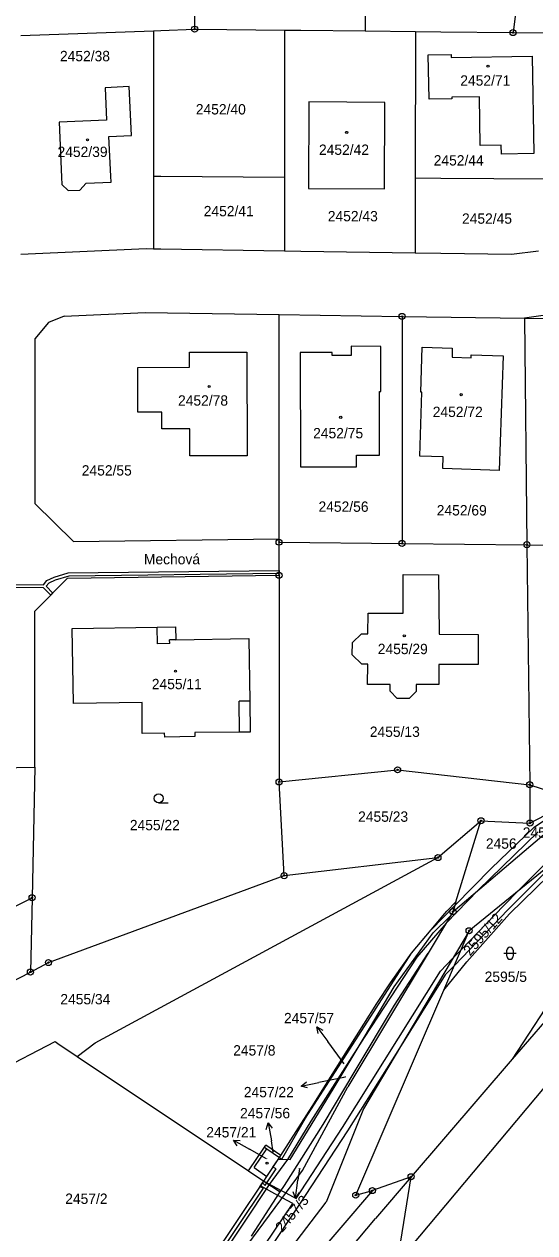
# Model space of a CAD drawing. Extents: x -755819 to -753140, y -1169796 to -1166000.
# Drawn here: x -754936.1 to -754852.2, y -1168641 to -1168442.4 of the extents above; entities that cross this region are included whole.
import ezdxf

# ---------------------------------------------------------------- set-up
doc = ezdxf.new("R2010")
doc.units = 0
for name, color, linetype in [('Vrstva 1', 7, 'Continuous'), ('Vrstva 15', 7, 'Continuous'), ('Vrstva 16', 7, 'Continuous'), ('Vrstva 18', 7, 'Continuous'), ('Vrstva 19', 7, 'Continuous'), ('Vrstva 24', 7, 'Continuous'), ('Vrstva 25', 7, 'Continuous'), ('Vrstva 27', 7, 'Continuous'), ('Vrstva 4', 7, 'Continuous'), ('Vrstva 6', 7, 'Continuous')]:
    doc.layers.add(name, color=color, linetype=linetype)

msp = doc.modelspace()

# ---------------------------------------------------------------- linework, layer by layer
at = {"layer": 'Vrstva 1'}
for p, q in [((-754880.09, -1168427.76), (-754880.09, -1168443.46)), ((-754853.78, -1168427.95), (-754855.8, -1168443.74)), ((-754908.13, -1168428.55), (-754908.12, -1168443.17)), ((-754936.66, -1168444.23), (-754914.89, -1168443.43)), ((-754914.89, -1168443.43), (-754914.9, -1168467.32)), ((-754914.89, -1168443.43), (-754913.66, -1168443.38)), ((-754913.66, -1168443.38), (-754908.12, -1168443.17)), ((-754908.12, -1168443.17), (-754907.52, -1168443.15)), ((-754907.52, -1168443.15), (-754893.33, -1168443.31)), ((-754893.33, -1168443.31), (-754893.33, -1168467.47)), ((-754893.33, -1168443.31), (-754890.66, -1168443.34)), ((-754890.66, -1168443.34), (-754880.09, -1168443.46)), ((-754880.09, -1168443.46), (-754871.83, -1168443.55)), ((-754871.83, -1168443.55), (-754871.86, -1168467.62)), ((-754871.83, -1168443.55), (-754867.66, -1168443.6)), ((-754867.66, -1168443.6), (-754855.8, -1168443.74)), ((-754855.8, -1168443.74), (-754850.66, -1168443.8)), ((-754869.74, -1168447.37), (-754865.99, -1168447.33)), ((-754869.6, -1168454.67), (-754869.74, -1168447.37)), ((-754865.99, -1168447.33), (-754865.98, -1168447.83)), ((-754865.98, -1168447.83), (-754852.68, -1168447.61)), ((-754852.68, -1168447.61), (-754852.37, -1168463.63)), ((-754918.86, -1168452.62), (-754922.84, -1168452.83)), ((-754922.84, -1168452.83), (-754922.59, -1168458.13)), ((-754918.51, -1168460.63), (-754918.86, -1168452.62)), ((-754889.36, -1168455.14), (-754889.43, -1168469.35)), ((-754876.85, -1168455.2), (-754889.36, -1168455.14)), ((-754876.92, -1168469.41), (-754876.85, -1168455.2)), ((-754865.84, -1168454.6), (-754869.6, -1168454.67)), ((-754861.34, -1168454.27), (-754865.84, -1168454.36)), ((-754865.84, -1168454.36), (-754865.84, -1168454.6)), ((-754861.19, -1168462.29), (-754861.34, -1168454.27)), ((-754922.59, -1168458.13), (-754930.41, -1168458.45)), ((-754930.41, -1168458.45), (-754929.99, -1168467.5)), ((-754922.21, -1168460.79), (-754918.51, -1168460.63)), ((-754921.89, -1168467.32), (-754922.21, -1168460.79)), ((-754857.75, -1168462.22), (-754861.19, -1168462.29)), ((-754857.72, -1168463.7), (-754857.75, -1168462.22)), ((-754852.37, -1168463.63), (-754857.72, -1168463.7)), ((-754929.99, -1168467.5), (-754929.93, -1168468.72)), ((-754921.84, -1168468.29), (-754921.89, -1168467.32)), ((-754914.9, -1168467.32), (-754914.9, -1168479.25)), ((-754893.33, -1168467.47), (-754893.33, -1168479.59)), ((-754871.86, -1168467.62), (-754871.88, -1168479.92)), ((-754929.93, -1168468.72), (-754928.89, -1168469.7)), ((-754928.89, -1168469.7), (-754927, -1168469.65)), ((-754927, -1168469.65), (-754925.97, -1168468.48)), ((-754925.97, -1168468.48), (-754921.84, -1168468.29)), ((-754889.43, -1168469.35), (-754876.92, -1168469.41)), ((-754936.66, -1168480.16), (-754916.09, -1168479.23)), ((-754916.09, -1168479.23), (-754914.9, -1168479.25)), ((-754914.9, -1168479.25), (-754913.66, -1168479.27)), ((-754913.66, -1168479.27), (-754893.33, -1168479.59)), ((-754893.33, -1168479.59), (-754890.66, -1168479.63)), ((-754890.66, -1168479.63), (-754871.88, -1168479.92)), ((-754856.07, -1168480.17), (-754851.63, -1168479.62)), ((-754871.88, -1168479.92), (-754867.66, -1168479.99)), ((-754867.66, -1168479.99), (-754856.07, -1168480.17)), ((-754932.11, -1168491.4), (-754934.39, -1168494.04)), ((-754929.55, -1168490.31), (-754932.11, -1168491.4)), ((-754894.24, -1168526.91), (-754894.24, -1168490.06)), ((-754874.03, -1168490.38), (-754874.03, -1168527.68)), ((-754847.13, -1168489.68), (-754853.92, -1168490.69)), ((-754853.92, -1168490.69), (-754853.54, -1168527.89)), ((-754934.39, -1168494.04), (-754934.37, -1168521.13)), ((-754882.4, -1168495.29), (-754882.41, -1168496.79)), ((-754877.54, -1168495.33), (-754882.4, -1168495.29)), ((-754877.53, -1168502.73), (-754877.54, -1168495.33)), ((-754870.96, -1168502.85), (-754870.73, -1168495.43)), ((-754870.73, -1168495.43), (-754865.78, -1168495.58)), ((-754908.98, -1168496.25), (-754899.54, -1168496.26)), ((-754908.98, -1168498.71), (-754908.98, -1168496.25)), ((-754899.54, -1168496.26), (-754899.49, -1168513.31)), ((-754890.76, -1168496.31), (-754890.75, -1168515.1)), ((-754885.51, -1168496.32), (-754890.76, -1168496.31)), ((-754885.52, -1168496.82), (-754885.51, -1168496.32)), ((-754882.41, -1168496.79), (-754885.52, -1168496.82)), ((-754865.78, -1168495.58), (-754865.83, -1168497.08)), ((-754865.83, -1168497.08), (-754862.7, -1168497.21)), ((-754862.7, -1168497.21), (-754862.69, -1168496.69)), ((-754862.69, -1168496.69), (-754857.45, -1168496.86)), ((-754857.45, -1168496.86), (-754858.08, -1168515.69)), ((-754917.47, -1168498.76), (-754908.98, -1168498.71)), ((-754917.43, -1168506.13), (-754917.47, -1168498.76)), ((-754877.74, -1168513.16), (-754877.73, -1168502.73)), ((-754877.73, -1168502.73), (-754877.53, -1168502.73)), ((-754871.11, -1168513.32), (-754870.77, -1168502.84)), ((-754870.77, -1168502.84), (-754870.96, -1168502.85)), ((-754913.53, -1168506.13), (-754917.43, -1168506.13)), ((-754913.53, -1168508.84), (-754913.53, -1168506.13)), ((-754908.9, -1168508.84), (-754913.53, -1168508.84)), ((-754908.91, -1168513.28), (-754908.9, -1168508.84)), ((-754899.49, -1168513.31), (-754908.91, -1168513.28)), ((-754881.54, -1168515.11), (-754881.54, -1168513.16)), ((-754881.54, -1168513.16), (-754877.74, -1168513.16)), ((-754867.3, -1168513.44), (-754871.11, -1168513.32)), ((-754890.75, -1168515.1), (-754881.54, -1168515.11)), ((-754867.36, -1168515.38), (-754867.3, -1168513.44)), ((-754858.08, -1168515.69), (-754867.36, -1168515.38)), ((-754934.37, -1168521.13), (-754928.02, -1168527.39)), ((-754928.02, -1168527.39), (-754894.24, -1168526.91)), ((-754894.24, -1168527.48), (-754894.24, -1168526.91)), ((-754894.24, -1168532.91), (-754894.24, -1168527.48)), ((-754894.24, -1168527.48), (-754874.03, -1168527.68)), ((-754874.03, -1168527.68), (-754853.54, -1168527.89)), ((-754853.54, -1168527.89), (-754853.07, -1168567.33)), ((-754929.02, -1168533.41), (-754894.24, -1168532.91)), ((-754894.24, -1168532.91), (-754894.24, -1168566.88)), ((-754873.88, -1168532.8), (-754868.06, -1168532.83)), ((-754873.86, -1168539.16), (-754873.88, -1168532.8)), ((-754868.06, -1168532.83), (-754867.96, -1168542.61)), ((-754934.37, -1168538.84), (-754929.02, -1168533.41)), ((-754934.37, -1168564.43), (-754934.37, -1168538.84)), ((-754879.67, -1168542.52), (-754879.6, -1168539.16)), ((-754879.6, -1168539.16), (-754873.86, -1168539.16)), ((-754928.22, -1168541.67), (-754914.26, -1168541.44)), ((-754928.02, -1168554.01), (-754928.22, -1168541.67)), ((-754914.26, -1168541.44), (-754911.26, -1168541.39)), ((-754911.26, -1168541.39), (-754911.23, -1168543.53)), ((-754882.18, -1168543.96), (-754880.71, -1168542.53)), ((-754880.71, -1168542.53), (-754879.67, -1168542.52)), ((-754867.96, -1168542.61), (-754861.55, -1168542.66)), ((-754861.55, -1168542.66), (-754861.56, -1168547.57)), ((-754911.23, -1168543.53), (-754899.22, -1168543.31)), ((-754899.22, -1168543.31), (-754899.08, -1168553.59)), ((-754882.23, -1168546.01), (-754882.18, -1168543.96)), ((-754880.67, -1168547.54), (-754882.23, -1168546.01)), ((-754879.69, -1168547.54), (-754880.67, -1168547.54)), ((-754879.7, -1168550.84), (-754879.69, -1168547.54)), ((-754861.56, -1168547.57), (-754867.99, -1168547.57)), ((-754867.99, -1168547.57), (-754867.99, -1168550.86)), ((-754876, -1168550.88), (-754879.7, -1168550.84)), ((-754876, -1168551.98), (-754876, -1168550.88)), ((-754867.99, -1168550.86), (-754871.7, -1168550.85)), ((-754871.7, -1168550.85), (-754871.7, -1168552.02)), ((-754874.86, -1168553.19), (-754876, -1168551.98)), ((-754871.7, -1168552.02), (-754872.87, -1168553.18)), ((-754916.72, -1168553.82), (-754928.02, -1168554.01)), ((-754916.73, -1168558.92), (-754916.72, -1168553.82)), ((-754899.08, -1168553.59), (-754899.02, -1168558.68)), ((-754872.87, -1168553.18), (-754874.86, -1168553.19)), ((-754913.05, -1168558.87), (-754916.73, -1168558.92)), ((-754913.04, -1168559.52), (-754913.05, -1168558.87)), ((-754900.76, -1168558.7), (-754908.1, -1168558.78)), ((-754908.1, -1168558.78), (-754908.09, -1168559.43)), ((-754899.02, -1168558.68), (-754900.76, -1168558.7)), ((-754908.09, -1168559.43), (-754913.04, -1168559.52)), ((-754823.37, -1168562.35), (-754855.93, -1168612.44)), ((-754940.37, -1168564.57), (-754934.37, -1168564.43)), ((-754934.37, -1168564.43), (-754934.84, -1168585.91)), ((-754894.24, -1168566.88), (-754874.77, -1168564.89)), ((-754874.77, -1168564.89), (-754853.07, -1168567.33)), ((-754893.41, -1168582.28), (-754894.24, -1168566.88)), ((-754865.67, -1168588.18), (-754841.3, -1168567.49)), ((-754853.07, -1168567.33), (-754853.02, -1168573.64)), ((-754853.07, -1168567.33), (-754846.47, -1168569.48)), ((-754853.02, -1168573.64), (-754847.71, -1168570.86)), ((-754868.15, -1168579.31), (-754861.07, -1168573.26)), ((-754865.18, -1168586.59), (-754861.07, -1168573.26)), ((-754841.97, -1168574.18), (-754863.02, -1168591.33)), ((-754861.07, -1168573.26), (-754853.02, -1168573.64)), ((-754856.41, -1168588.57), (-754846.14, -1168578.51)), ((-754893.41, -1168582.28), (-754868.15, -1168579.31)), ((-754932.14, -1168596.57), (-754893.41, -1168582.28)), ((-754956.25, -1168596.56), (-754934.84, -1168585.91)), ((-754934.84, -1168585.91), (-754935.11, -1168598.12)), ((-754866.68, -1168588.14), (-754865.18, -1168586.59)), ((-754865.18, -1168586.59), (-754865.67, -1168588.18)), ((-754866.09, -1168588.88), (-754869.77, -1168595.01)), ((-754868.95, -1168591.66), (-754866.09, -1168588.88)), ((-754867.34, -1168588.91), (-754866.68, -1168588.14)), ((-754865.67, -1168588.18), (-754866.09, -1168588.88)), ((-754863.4, -1168596.43), (-754856.41, -1168588.57)), ((-754869.28, -1168591.19), (-754867.34, -1168588.91)), ((-754863.02, -1168591.33), (-754880.39, -1168620.6)), ((-754875.31, -1168600.54), (-754868.95, -1168591.66)), ((-754872.47, -1168595.03), (-754869.28, -1168591.19)), ((-754867.2, -1168601.08), (-754863.02, -1168591.33)), ((-754935.11, -1168598.12), (-754932.14, -1168596.57)), ((-754869.77, -1168595.01), (-754882.97, -1168617.01)), ((-754875.26, -1168603.56), (-754869.77, -1168595.01)), ((-754874.23, -1168597.47), (-754872.47, -1168595.03)), ((-754867.2, -1168601.08), (-754863.4, -1168596.43)), ((-754958.84, -1168610.5), (-754935.11, -1168598.12)), ((-754875.94, -1168599.92), (-754874.23, -1168597.47)), ((-754843.65, -1168598.15), (-754855.93, -1168612.44)), ((-754880.25, -1168608.87), (-754875.31, -1168600.54)), ((-754878.18, -1168603.28), (-754875.94, -1168599.92)), ((-754881.65, -1168634.79), (-754867.2, -1168601.08)), ((-754872.54, -1168643.22), (-754838.5, -1168602.56)), ((-754881.76, -1168614.34), (-754875.26, -1168603.56)), ((-754880.3, -1168606.67), (-754878.18, -1168603.28)), ((-754884.86, -1168613.94), (-754880.3, -1168606.67)), ((-754954.61, -1168621.83), (-754931.06, -1168609.54)), ((-754931.06, -1168609.54), (-754930.59, -1168609.86)), ((-754930.59, -1168609.86), (-754927.41, -1168611.98)), ((-754885.36, -1168617.39), (-754880.25, -1168608.87)), ((-754927.41, -1168611.98), (-754899.25, -1168630.79)), ((-754855.93, -1168612.44), (-754872.55, -1168631.77)), ((-754888.83, -1168620.19), (-754884.86, -1168613.94)), ((-754887.02, -1168623.19), (-754881.76, -1168614.34)), ((-754892.43, -1168628.94), (-754885.36, -1168617.39)), ((-754890.42, -1168630.76), (-754882.97, -1168617.01)), ((-754892.31, -1168625.67), (-754888.83, -1168620.19)), ((-754880.39, -1168620.6), (-754886.53, -1168635.92)), ((-754893.37, -1168633.21), (-754887.02, -1168623.19)), ((-754896.67, -1168626.92), (-754896.45, -1168626.59)), ((-754893.95, -1168628.26), (-754896.45, -1168626.59)), ((-754893.95, -1168628.26), (-754892.31, -1168625.67)), ((-754899.25, -1168630.79), (-754896.67, -1168626.92)), ((-754896.67, -1168626.92), (-754896.25, -1168627.2)), ((-754896.25, -1168627.2), (-754894.17, -1168628.59)), ((-754896.24, -1168631.7), (-754894.17, -1168628.59)), ((-754894.17, -1168628.59), (-754893.95, -1168628.26)), ((-754894.17, -1168628.59), (-754893.77, -1168628.87)), ((-754893.77, -1168628.87), (-754892.43, -1168628.94)), ((-754914.03, -1168658.33), (-754896.75, -1168632.46)), ((-754905.02, -1168650.51), (-754890.42, -1168630.76)), ((-754899.25, -1168630.79), (-754896.75, -1168632.46)), ((-754896.75, -1168632.46), (-754896.24, -1168631.7)), ((-754896.75, -1168632.46), (-754894.06, -1168634.26)), ((-754872.55, -1168631.77), (-754878.91, -1168634.04)), ((-754872.55, -1168631.77), (-754878.42, -1168638.6)), ((-754898.8, -1168641.53), (-754894.06, -1168634.26)), ((-754894.06, -1168634.26), (-754893.37, -1168633.21)), ((-754881.65, -1168634.79), (-754878.91, -1168634.04)), ((-754921.66, -1168682.14), (-754886.53, -1168635.92)), ((-754902.48, -1168667.31), (-754878.42, -1168638.6))]:
    msp.add_line(p, q, dxfattribs=at)
at = {"layer": 'Vrstva 16'}
for p, q in [((-754888.04, -1168607.14), (-754886.25, -1168609.55)), ((-754883.53, -1168613.2), (-754886.25, -1168609.55)), ((-754890.64, -1168616.85), (-754887.7, -1168616.26)), ((-754883.36, -1168615.38), (-754887.7, -1168616.26)), ((-754896.03, -1168622.9), (-754895.52, -1168625.86)), ((-754901.74, -1168625.74), (-754899.12, -1168627.21)), ((-754895.2, -1168627.72), (-754895.52, -1168625.86)), ((-754896.29, -1168628.8), (-754899.12, -1168627.21)), ((-754890.88, -1168630.41), (-754891.15, -1168632.31)), ((-754891.56, -1168635.28), (-754891.15, -1168632.31))]:
    msp.add_line(p, q, dxfattribs=at)
for points in [[(-754887.84, -1168608.24), (-754888.04, -1168607.14), (-754887.04, -1168607.65)], [(-754889.56, -1168617.15), (-754890.64, -1168616.85), (-754889.76, -1168616.17)], [(-754896.35, -1168623.97), (-754896.03, -1168622.9), (-754895.36, -1168623.8)], [(-754901.11, -1168626.67), (-754901.74, -1168625.74), (-754900.62, -1168625.79)], [(-754890.93, -1168634.36), (-754891.56, -1168635.28), (-754891.92, -1168634.22)]]:
    msp.add_lwpolyline(points, dxfattribs=at)
at = {"layer": 'Vrstva 24'}
for centre, radius in [((-754908.12, -1168443.17), 0.5), ((-754908.12, -1168443.17), 0.1), ((-754855.8, -1168443.74), 0.5), ((-754855.8, -1168443.74), 0.1), ((-754874.03, -1168490.38), 0.5), ((-754874.03, -1168490.38), 0.1), ((-754894.24, -1168527.48), 0.5), ((-754874.03, -1168527.68), 0.5), ((-754894.24, -1168527.48), 0.1), ((-754874.03, -1168527.68), 0.1), ((-754853.54, -1168527.89), 0.5), ((-754853.54, -1168527.89), 0.1), ((-754894.24, -1168532.91), 0.5), ((-754894.24, -1168532.91), 0.1), ((-754874.77, -1168564.89), 0.5), ((-754874.77, -1168564.89), 0.1), ((-754894.24, -1168566.88), 0.5), ((-754894.24, -1168566.88), 0.1), ((-754853.07, -1168567.33), 0.5), ((-754853.07, -1168567.33), 0.1), ((-754861.07, -1168573.26), 0.5), ((-754861.07, -1168573.26), 0.1), ((-754853.02, -1168573.64), 0.5), ((-754853.02, -1168573.64), 0.1), ((-754868.15, -1168579.31), 0.5), ((-754868.15, -1168579.31), 0.1), ((-754893.41, -1168582.28), 0.5), ((-754893.41, -1168582.28), 0.1), ((-754934.84, -1168585.91), 0.5), ((-754934.84, -1168585.91), 0.1), ((-754865.67, -1168588.18), 0.5), ((-754865.67, -1168588.18), 0.1), ((-754863.02, -1168591.33), 0.5), ((-754863.02, -1168591.33), 0.1), ((-754932.14, -1168596.57), 0.5), ((-754932.14, -1168596.57), 0.1), ((-754935.11, -1168598.12), 0.5), ((-754935.11, -1168598.12), 0.1), ((-754872.55, -1168631.77), 0.5), ((-754872.55, -1168631.77), 0.1), ((-754881.65, -1168634.79), 0.5), ((-754878.91, -1168634.04), 0.5), ((-754878.91, -1168634.04), 0.1), ((-754881.65, -1168634.79), 0.1)]:
    msp.add_circle(centre, radius, dxfattribs=at)
at = {"layer": 'Vrstva 25'}
for p, q in [((-754914.05, -1168570.33), (-754912.45, -1168570.33)), ((-754856.81, -1168595.53), (-754856.81, -1168594.53)), ((-754855.81, -1168594.53), (-754855.81, -1168595.53)), ((-754857.31, -1168595.03), (-754855.31, -1168595.03))]:
    msp.add_line(p, q, dxfattribs=at)
for centre, radius in [((-754859.91, -1168449.24), 0.175), ((-754925.74, -1168461.37), 0.175), ((-754883.14, -1168460.14), 0.175), ((-754905.73, -1168501.89), 0.175), ((-754864.33, -1168503.23), 0.175), ((-754884.12, -1168506.96), 0.175), ((-754873.67, -1168542.86), 0.175), ((-754911.26, -1168548.67), 0.175), ((-754914.05, -1168569.58), 0.75), ((-754896.22, -1168629.54), 0.175)]:
    msp.add_circle(centre, radius, dxfattribs=at)
for centre, start, end in [((-754856.31, -1168594.53), 0, 180), ((-754856.31, -1168595.53), 180, 0)]:
    msp.add_arc(centre, 0.5, start, end, dxfattribs=at)
at = {"layer": 'Vrstva 27'}
for p, q in [((-754932.41, -1168533.79), (-754931.22, -1168533.25)), ((-754931.22, -1168533.25), (-754928.9, -1168532.54)), ((-754928.82, -1168533.04), (-754931.04, -1168533.71)), ((-754928.9, -1168532.54), (-754894.24, -1168532.12)), ((-754894.24, -1168532.65), (-754928.82, -1168533.04)), ((-754894.24, -1168532.12), (-754894.24, -1168532.65)), ((-754939.74, -1168534.45), (-754932.97, -1168534.48)), ((-754932.96, -1168534.98), (-754939.74, -1168534.95)), ((-754932.97, -1168534.48), (-754932.41, -1168533.79)), ((-754931.77, -1168536.2), (-754932.96, -1168534.98)), ((-754932.09, -1168534.19), (-754932.52, -1168534.71)), ((-754932.52, -1168534.71), (-754931.42, -1168535.84)), ((-754931.04, -1168533.71), (-754932.09, -1168534.19)), ((-754931.42, -1168535.84), (-754931.77, -1168536.2)), ((-754852.32, -1168574.31), (-754845.62, -1168569.76)), ((-754854.83, -1168584.66), (-754842.48, -1168572.24)), ((-754859.42, -1168581.1), (-754852.32, -1168574.31)), ((-754851.68, -1168575.09), (-754861.53, -1168584.67)), ((-754847.37, -1168578.58), (-754856.6, -1168587.86)), ((-754865.36, -1168587.18), (-754859.42, -1168581.1)), ((-754861.53, -1168584.67), (-754866.8, -1168590.07)), ((-754857.32, -1168587.16), (-754854.83, -1168584.66)), ((-754869.28, -1168591.19), (-754865.36, -1168587.18)), ((-754856.6, -1168587.86), (-754865.49, -1168597.08)), ((-754864.38, -1168594.5), (-754857.32, -1168587.16)), ((-754866.8, -1168590.07), (-754871.61, -1168595.66)), ((-754872.47, -1168595.03), (-754869.28, -1168591.19)), ((-754865.74, -1168595.91), (-754864.38, -1168594.5)), ((-754889.89, -1168622.12), (-754872.47, -1168595.03)), ((-754871.61, -1168595.66), (-754880.25, -1168608.87)), ((-754867.71, -1168597.96), (-754865.74, -1168595.91)), ((-754883.82, -1168623.68), (-754867.71, -1168597.96)), ((-754866.93, -1168598.58), (-754874.48, -1168610.64)), ((-754865.49, -1168597.08), (-754866.93, -1168598.58)), ((-754880.25, -1168608.87), (-754889.04, -1168622.64)), ((-754874.48, -1168610.64), (-754882.98, -1168624.22)), ((-754893.77, -1168628.87), (-754889.89, -1168622.12)), ((-754889.04, -1168622.64), (-754892.87, -1168628.92)), ((-754891.46, -1168635.33), (-754883.82, -1168623.68)), ((-754882.98, -1168624.22), (-754890.89, -1168636.28)), ((-754896.27, -1168632.78), (-754894.71, -1168630.44)), ((-754892.87, -1168628.92), (-754895.85, -1168633.06)), ((-754895.25, -1168630.21), (-754894.41, -1168628.95)), ((-754894.71, -1168630.44), (-754895.25, -1168630.21)), ((-754894.41, -1168628.95), (-754893.77, -1168628.87)), ((-754896.96, -1168632.77), (-754896.75, -1168632.46)), ((-754896.75, -1168632.46), (-754893.9, -1168634.01)), ((-754912.6, -1168657.21), (-754896.83, -1168633.62)), ((-754895.85, -1168633.06), (-754912.18, -1168657.49)), ((-754897.4, -1168633.44), (-754896.96, -1168632.77)), ((-754896.83, -1168633.62), (-754897.4, -1168633.44)), ((-754897.29, -1168633.27), (-754896.96, -1168632.77)), ((-754894.43, -1168634.83), (-754897.29, -1168633.27)), ((-754896.96, -1168632.77), (-754896.55, -1168633.21)), ((-754896.55, -1168633.21), (-754896.27, -1168632.78)), ((-754893.9, -1168634.01), (-754893.13, -1168634.42)), ((-754893.13, -1168634.42), (-754891.46, -1168635.33)), ((-754907.17, -1168658.61), (-754892.01, -1168636.16)), ((-754890.89, -1168636.28), (-754906.33, -1168659.17)), ((-754893.72, -1168635.22), (-754894.43, -1168634.83)), ((-754892.01, -1168636.16), (-754893.72, -1168635.22))]:
    msp.add_line(p, q, dxfattribs=at)
at = {"layer": 'Vrstva 4'}
for p, q in [((-754914.21, -1168544.18), (-754914.26, -1168541.44)), ((-754912.22, -1168544.15), (-754914.21, -1168544.18)), ((-754911.23, -1168543.53), (-754912.23, -1168543.55)), ((-754912.22, -1168544.15), (-754912.23, -1168543.55)), ((-754899.08, -1168553.59), (-754900.83, -1168553.61)), ((-754900.76, -1168558.7), (-754900.83, -1168553.61)), ((-754898.36, -1168630.23), (-754896.25, -1168627.2)), ((-754898.36, -1168630.23), (-754896.24, -1168631.7))]:
    msp.add_line(p, q, dxfattribs=at)
at = {"layer": 'Vrstva 6'}
for p, q in [((-754914.9, -1168467.32), (-754913.66, -1168467.33)), ((-754913.66, -1168467.33), (-754893.33, -1168467.47)), ((-754871.86, -1168467.62), (-754867.66, -1168467.65)), ((-754867.66, -1168467.65), (-754850.27, -1168467.77)), ((-754929.55, -1168490.31), (-754916.26, -1168489.71)), ((-754916.26, -1168489.71), (-754894.24, -1168490.06)), ((-754894.24, -1168490.06), (-754874.03, -1168490.38)), ((-754874.03, -1168490.38), (-754853.92, -1168490.69)), ((-754853.92, -1168490.69), (-754826.05, -1168491.13)), ((-754853.54, -1168527.89), (-754830.27, -1168528.13)), ((-754924.47, -1168609.77), (-754868.15, -1168579.31)), ((-754927.41, -1168611.98), (-754924.47, -1168609.77)), ((-754874.8, -1168645.93), (-754872.55, -1168631.77)), ((-754878.91, -1168634.04), (-754890.83, -1168647.93))]:
    msp.add_line(p, q, dxfattribs=at)

# ---------------------------------------------------------------- texts
at = {"layer": 'Vrstva 15'}
msp.add_text('Mechová', height=1.7, dxfattribs=at).set_placement((-754916.46, -1168531.12))
at = {"layer": 'Vrstva 16'}
for s, p in [('2455/36', (-754854.21, -1168576.05)), ('2457/57', (-754893.44, -1168606.54)), ('2457/22', (-754900.04, -1168618.7)), ('2457/56', (-754900.66, -1168622.16)), ('2457/21', (-754906.21, -1168625.3))]:
    msp.add_text(s, height=1.7, dxfattribs=at).set_placement(p)
msp.add_text('2457/3', height=1.7, rotation=49.5609, dxfattribs=at).set_placement((-754893.74, -1168641.01))
at = {"layer": 'Vrstva 18'}
for s, height, p in [('2452/38', 1.7, (-754930.25, -1168448.44)), ('2452/40', 1.7, (-754907.93, -1168457.19)), ('2452/44', 1.7, (-754868.84, -1168465.58)), ('2452/41', 1.7, (-754906.63, -1168473.92)), ('2452/43', 1.7, (-754886.24, -1168474.75)), ('2452/45', 1.7, (-754864.19, -1168475.15)), ('2452/55', 1.7, (-754926.67, -1168516.53)), ('2452/56', 1.7, (-754887.77, -1168522.49)), ('2452/69', 1.7, (-754868.34, -1168523.09)), ('2455/13', 1.7, (-754879.34, -1168559.48)), ('2455/23', 1.7, (-754881.26, -1168573.43)), ('2455/22', 1.7, (-754918.77, -1168574.82)), ('2456', 1.7, (-754860.27, -1168577.86)), ('2595/5', 1.7, (-754860.47, -1168599.74)), ('2455/34', 1.7, (-754930.19, -1168603.43)), ('2457/8', 1.7, (-754901.79, -1168611.84)), ('2457/57', 0.1, (-754883.82, -1168613.2)), ('2457/22', 0.1, (-754883.66, -1168615.38)), ('2457/56', 0.1, (-754895.49, -1168627.72)), ('2457/3', 0.1, (-754891.13, -1168630.41)), ('2457/2', 1.7, (-754929.39, -1168636.22))]:
    msp.add_text(s, height=height, dxfattribs=at).set_placement(p)
msp.add_text('2595/12', height=1.7, rotation=48.7014, dxfattribs=at).set_placement((-754862.86, -1168595.56))
at = {"layer": 'Vrstva 19'}
for s, height, p in [('2452/71', 1.7, (-754864.47, -1168452.46)), ('2452/39', 1.7, (-754930.65, -1168464.18)), ('2452/42', 1.7, (-754887.69, -1168463.83)), ('2452/78', 1.7, (-754910.85, -1168505.04)), ('2452/72', 1.7, (-754869, -1168506.91)), ('2452/75', 1.7, (-754888.65, -1168510.41)), ('2455/29', 1.7, (-754878.03, -1168545.88)), ('2455/11', 1.7, (-754915.16, -1168551.64)), ('2457/21', 0.1, (-754896.56, -1168628.8))]:
    msp.add_text(s, height=height, dxfattribs=at).set_placement(p)

doc.saveas('drawing.dxf')
